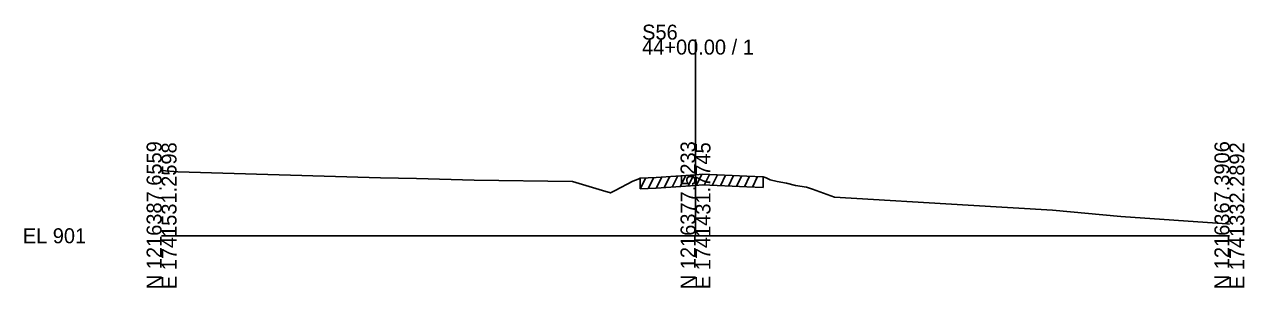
# Model space of a CAD drawing. Extents: x -26 to 1203, y -10 to 19541.
# Drawn here: x -25.7 to 202.8, y 18990.3 to 19039.5 of the extents above; entities that cross this region are included whole.
import ezdxf

# ---------------------------------------------------------------- set-up
doc = ezdxf.new("R2010")
doc.units = 0
for name, color, linetype in [('RD_GPK_XS_Cell', 7, 'Continuous'), ('RD_XS_ExGround', 7, 'Continuous'), ('RD_XS_ExPaveRet', 7, 'Continuous'), ('RD_XS_TX_Elev_EX', 7, 'Continuous')]:
    doc.layers.add(name, color=color, linetype=linetype)

msp = doc.modelspace()

# ---------------------------------------------------------------- linework, layer by layer
at = {"layer": 'RD_GPK_XS_Cell'}
for p, q in [((100, 19000), (100, 19036.7)), ((0, 19000), (100, 19000)), ((100, 19000), (200, 19000))]:
    msp.add_line(p, q, dxfattribs=at)
at = {"layer": 'RD_XS_ExGround'}
msp.add_lwpolyline([(0, 19012.23), (3.05, 19011.96), (40.97, 19010.81), (47.75, 19010.7), (58.53, 19010.38), (76.98, 19010.13), (82.58, 19008.44), (84.06, 19008.02), (84.94, 19008.48), (88.26, 19010.24), (89.24, 19010.62), (89.65, 19010.75), (92.65, 19010.92), (100, 19011.41), (101.34, 19011.5), (109.64, 19011.14), (112.67, 19011.03), (113.22, 19010.84), (113.99, 19010.45), (115.32, 19010.16), (117.05, 19009.82), (118.71, 19009.38), (120.77, 19009.12), (121.9, 19008.71), (126.02, 19007.23), (151.04, 19005.71), (166.88, 19004.79), (179.67, 19003.63), (199.49, 19002.22), (200, 19002.19)], dxfattribs=at)
at = {"layer": 'RD_XS_ExPaveRet'}
for p, q in [((89.65, 19008.75), (90.68, 19010.81)), ((89.65, 19008.75), (89.65, 19010.75)), ((91.15, 19008.84), (92.18, 19010.9)), ((92.65, 19008.92), (93.69, 19010.99)), ((92.65, 19008.92), (100, 19009.41)), ((94.15, 19009.02), (95.19, 19011.09)), ((95.65, 19009.12), (96.69, 19011.19)), ((97.15, 19009.22), (98.19, 19011.29)), ((98.65, 19009.32), (99.69, 19011.39)), ((100, 19009.41), (101.34, 19009.5)), ((100.15, 19009.42), (101.19, 19011.49)), ((101.34, 19009.5), (109.64, 19009.14)), ((101.65, 19009.49), (102.63, 19011.45)), ((103.15, 19009.42), (104.13, 19011.38)), ((104.65, 19009.36), (105.63, 19011.31)), ((106.15, 19009.29), (107.13, 19011.25)), ((107.65, 19009.23), (108.63, 19011.18)), ((109.15, 19009.16), (110.13, 19011.12)), ((110.65, 19009.1), (111.64, 19011.07)), ((112.67, 19011.03), (112.67, 19009.03)), ((89.65, 19008.75), (92.65, 19008.92)), ((109.64, 19009.14), (112.67, 19009.03))]:
    msp.add_line(p, q, dxfattribs=at)

# ---------------------------------------------------------------- texts
at = {"layer": 'RD_GPK_XS_Cell'}
for s, p in [('S56', (90, 19036.7)), ('44+00.00 / 1', (90, 19033.9)), ('EL 901', (-26, 18998.6))]:
    msp.add_text(s, height=2.8, dxfattribs=at).set_placement(p)
for s, p in [('N 1216387.6559', (0, 18990)), ('E 1741531.2598', (2.8, 18990)), ('N 1216377.5233', (100, 18990)), ('E 1741431.7745', (102.8, 18990)), ('N 1216367.3906', (200, 18990)), ('E 1741332.2892', (202.8, 18990))]:
    msp.add_text(s, height=2.8, rotation=90, dxfattribs=at).set_placement(p)
at = {"layer": 'RD_XS_TX_Elev_EX'}
msp.add_text('906.71', height=0.1, rotation=90, dxfattribs=at).set_placement((100.1, 19011.41))

doc.saveas('drawing.dxf')
